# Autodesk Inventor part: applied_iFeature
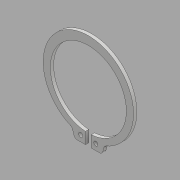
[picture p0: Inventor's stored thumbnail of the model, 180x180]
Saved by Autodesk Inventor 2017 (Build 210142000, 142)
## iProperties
Created: 2016-06
Part Number: applied_iFeature
Material: Generic
Document SubType Name: Modeling
Designer: CADCIM
Density: 1 g/cm^3
Appearance: Default
Author: CADCIM
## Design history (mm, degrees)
sketch "Sketch1"
  geometry: L1 (9.452, -25.542)-(8.665, -28.284); L2 (6.743, -29.733)-(1.75, -29.733); L3 (1.75, -29.733)-(1.75, -22.833); L4 (0, 0)-(0, -33.55); L5 (-6.743, -29.733)-(-1.75, -29.733); L6 (-1.75, -29.733)-(-1.75, -22.833); L7 (-9.452, -25.542)-(-8.665, -28.284); C1 r 1.25 at (4.55, -26.017); C2 r 1.25 at (-4.55, -26.017); A1 r 22.9 centre (0, 0) between (1.75, -22.833) and (-1.75, -22.833); A2 r 27.2 centre (0, 0.8) between (10.595, -24.252) and (-10.595, -24.252); A3 r 2 centre (-6.743, -27.733) between (-8.665, -28.284) and (-6.743, -29.733); A4 r 2 centre (-11.374, -26.094) between (-9.452, -25.542) and (-10.595, -24.252); A5 r 2 centre (11.374, -26.094) between (10.595, -24.252) and (9.452, -25.542); A6 r 2 centre (6.743, -27.733) between (6.743, -29.733) and (8.665, -28.284); 12 further points
  constraints: 18 point on circle, 14 end point, 8 centre point, 8 point on line, 8 tangent, 4 equal radius, 4 symmetric about line, 2 coincident, 2 midpoint, 1 horizontal, 1 horizontal alignment, 1 perpendicular, 1 vertical
  dimensions: "d0" = 45.8 diameter of A1; "d4" = 6.9 distance from line of L6.end L5; "d5" = 5.1 distance of point (0, 28) point (0, 22.9); "d6" = 2.5 diameter of C1; "d8" = 2 radius of A3 (derived); "d9" = 2.8 distance from line of C1.centre L3; "d10" = 3.5 distance of L5.end L2.end; "d11" = 27.2 radius of A2; "d14" = 6.5 distance of L5.end point (-8.25, -29.733); "d15" = 32 deg angle of L7 L1
extrude "Extrusion1" new body sketch "Sketch1" distance "d16" = 2; taper "d17" = 0 deg
body "Solid1"
